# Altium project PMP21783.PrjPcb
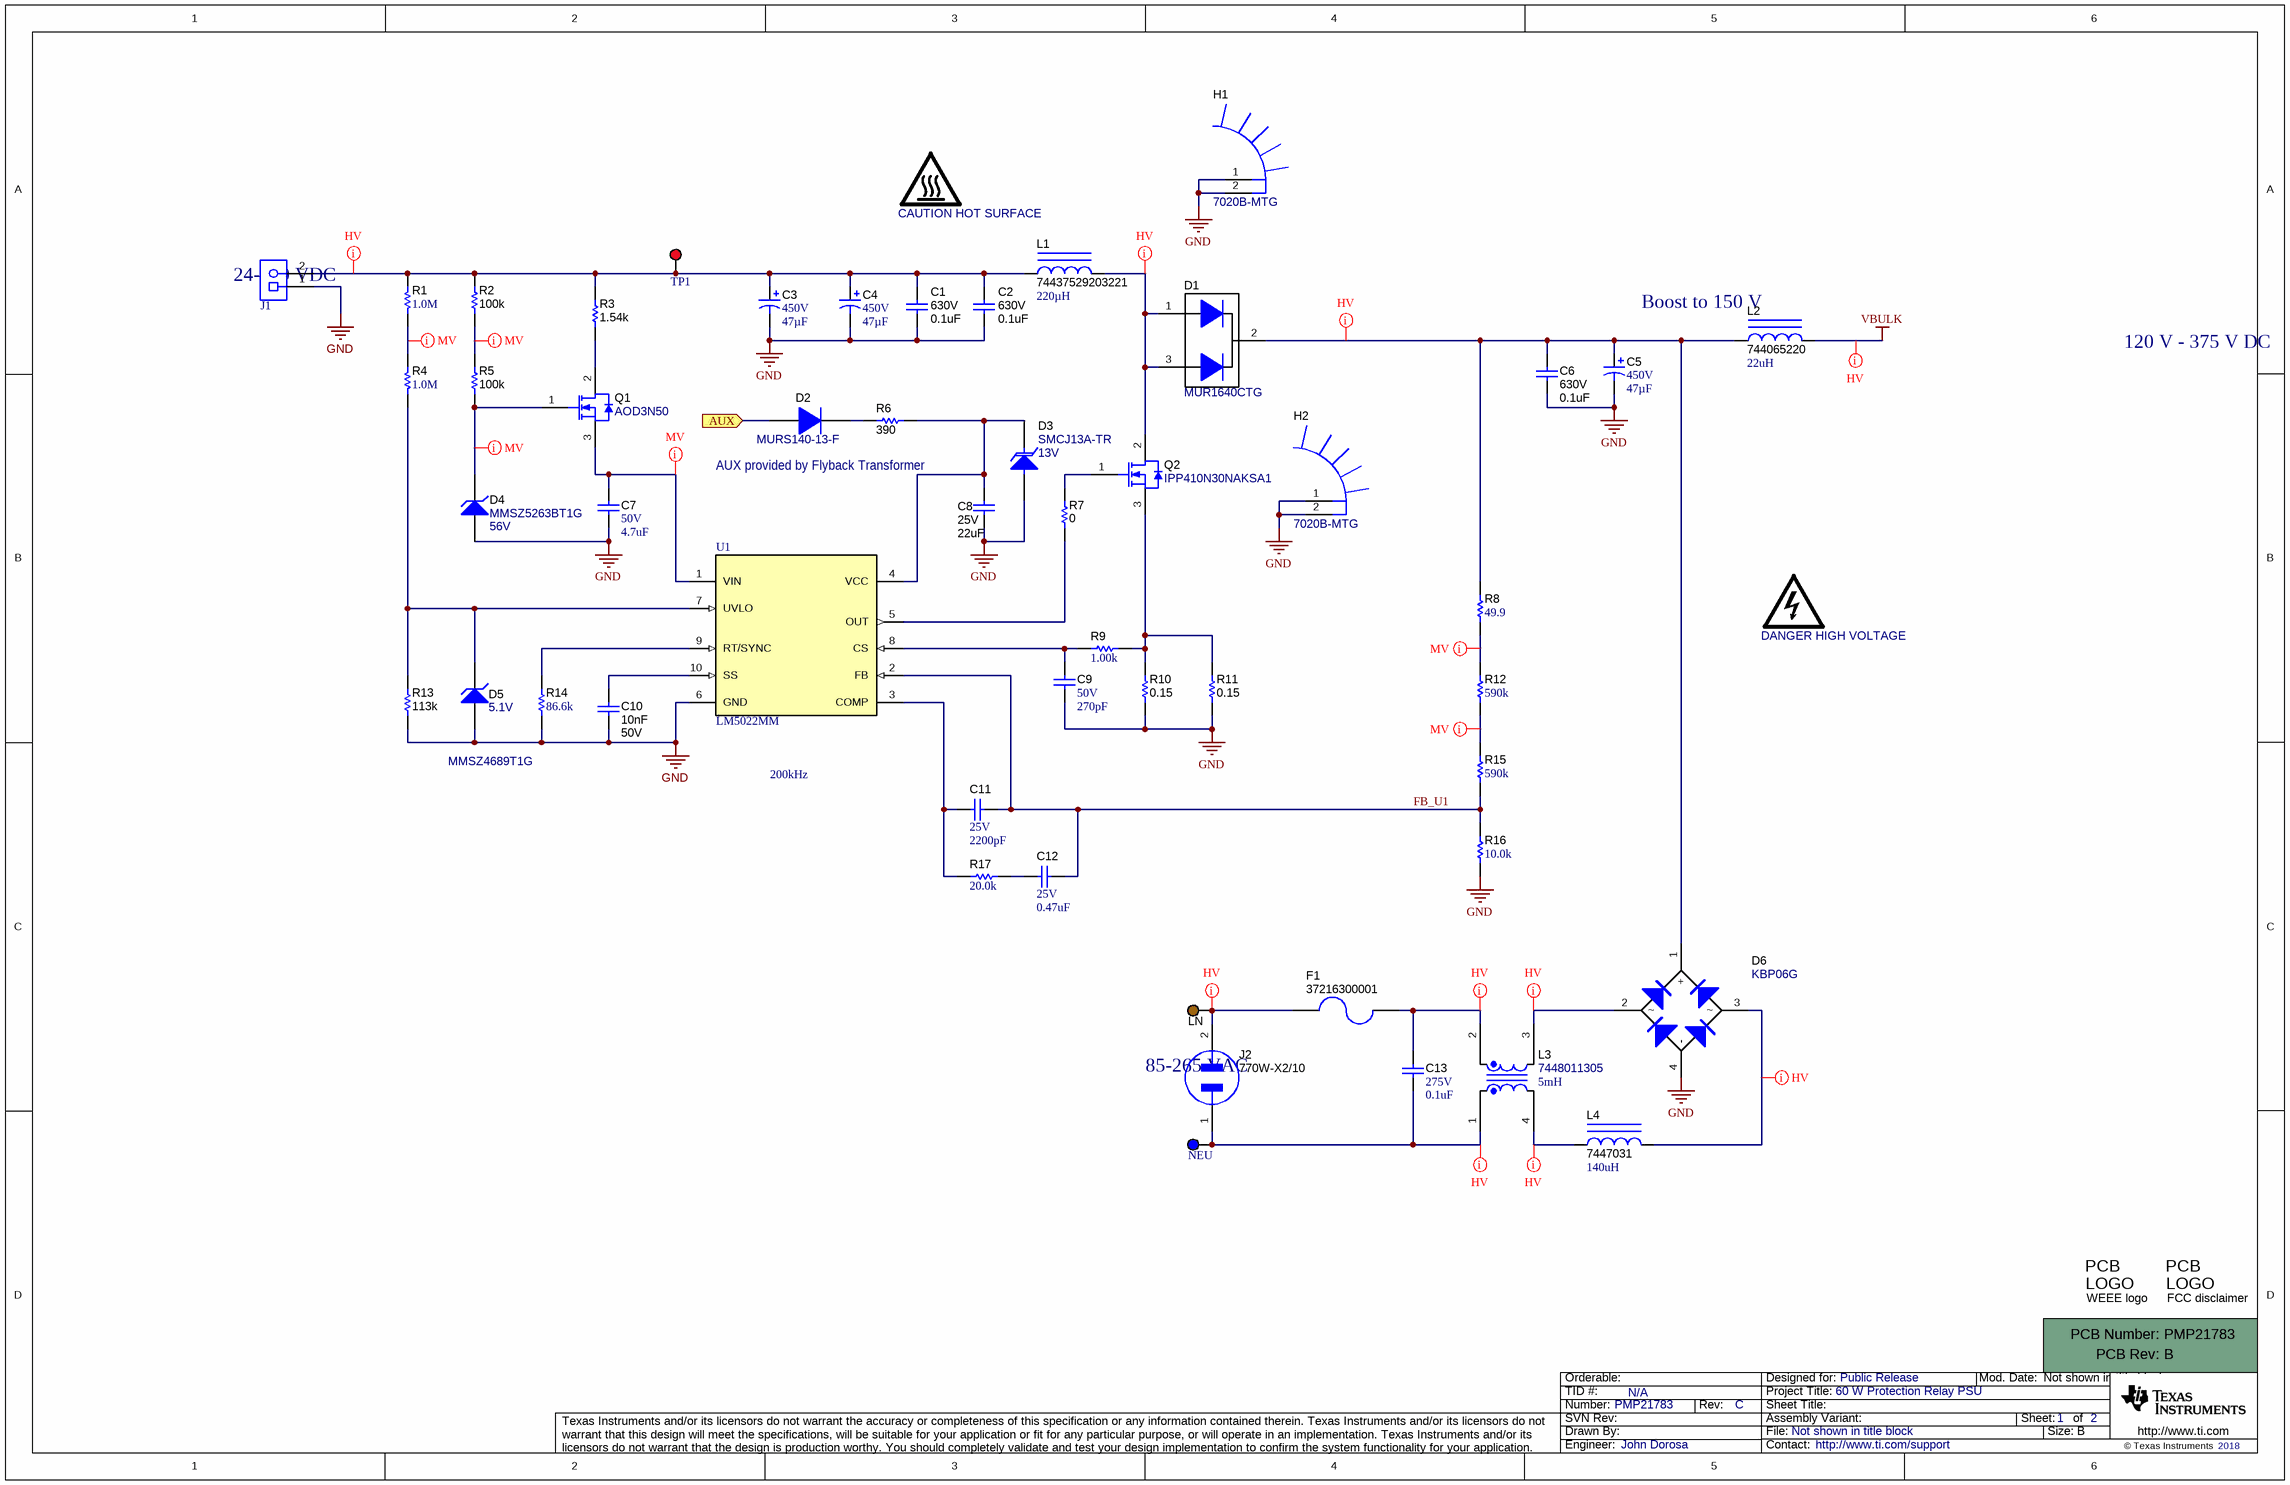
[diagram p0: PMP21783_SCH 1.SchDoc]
TID: N/A; TechSupport: http://www.ti.com/support; SCH_Rev: C; PRJ_Title: 60 W Protection Relay PSU; PRJ_Number: PMP21783; PRJ_Engineer: John Dorosa; PRJ_Customer: Public Release; PCB_Rev: B; PCB_Layout: John Dorosa; CopyrightYear: 2018
2 sheets, 146 parts. Net scope: flat (ports and power ports of the same name join across sheets).
Board file: PMP21783_PCB.PcbDoc
Sheets:
  PMP21783_SCH 1.SchDoc
  PMP21783_SCH 2.SchDoc

## Sheet PMP21783_SCH 1.SchDoc
size 431 x 279 mm; Date: Not shown in title block; ApprovedBy: Not shown in title block; CheckedBy: Not shown in title block; Author: Not shown in title block; CompanyName: Not shown in title block; Engineer: Not shown in title block; Organization: Not shown in title block; Address1: Not shown in title block; Address2: Not shown in title block; Address3: Not shown in title block; Address4: Not shown in title block; DocumentNumber: 1; Revision: Use project parameter SCH_Rev; SheetNumber: 1; SheetTotal: 2; PageSetup: Record=PageOptions¦CenterHorizontal=True¦CenterVertical=True¦PrintScale=1.00¦XCorrection=1.00¦YCorrection=1.00¦PrintKind=0¦BorderSize=5000000¦LeftOffset=0¦BottomOffset=0¦Orientation=2¦PaperLength=1000¦PaperWidth=1000¦Scale=100¦PaperSource=15¦PrintQuality=600¦MediaType=1¦DitherType=10¦PaperKind=Letter¦PrintScaleMode=1

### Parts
!PCB1  Printed Circuit Board  (value not drawn)  (mechanical)
C1  VDC_V: 630V  ValueDisplayed: 0.1uF  [1210_280]  (hidden comment: C1210C104KBRAC7800)
C2  VDC_V: 630V  ValueDisplayed: 0.1uF  [1210_280]  (hidden comment: C1210C104KBRAC7800)
C3  VDC_V: 450V  ValueDisplayed: 47µF  [BXW_1250x3500]  (hidden comment: 450BXW47MEFC12.5X35)
C4  VDC_V: 450V  ValueDisplayed: 47µF  [BXW_1250x3500]  (hidden comment: 450BXW47MEFC12.5X35)
C5  VDC_V: 450V  ValueDisplayed: 47µF  [BXW_1250x3500]  (hidden comment: 450BXW47MEFC12.5X35)
C6  VDC_V: 630V  ValueDisplayed: 0.1uF  [1210_280]  (hidden comment: C1210C104KBRAC7800)
C7  VDC_V: 50V  ValueDisplayed: 4.7uF  [1206_180]  (hidden comment: GRM31CR71H475KA12L)
C8  VDC_V: 25V  ValueDisplayed: 22uF  [1206_190]  (hidden comment: EMK316BB7226ML-T)
C9  VDC_V: 50V  ValueDisplayed: 270pF  [0603]  (hidden comment: GRM188R71H271KA01D)
C10  Cap_F: 10nF  VDC_V: 50V  [0603]  (hidden comment: GRM188R71H103KA01D)
C11  VDC_V: 25V  ValueDisplayed: 2200pF  [0603]  (hidden comment: GRM188R71E222KA01D)
C12  VDC_V: 25V  ValueDisplayed: 0.47uF  [0603]  (hidden comment: GRM188R71E474KA12D)
C13  VDC_V: 275V  ValueDisplayed: 0.1uF  [WCAP-FTX2_1800x600x1200]  (hidden comment: 890324025017)
D1  MUR1640CTG  [TO-220AB]
D2  MURS140-13-F  [SMB]
D3  SMCJ13A-TR  value 13V  [SMC]
D4  MMSZ5263BT1G  value 56V  [SOD-123]
D5  MMSZ4689T1G  value 5.1V  [SOD-123]
D6  KBP06G  [KBP]
F1  37216300001  [FUSE_372]
H1  7020B-MTG  [FP-7020B-MTG_HEAT_SINK_TO220-MFG]
H2  7020B-MTG  [FP-7020B-MTG_HEAT_SINK_TO220-MFG]
J1  ED120/2DS  [On-Shore_ED120_2DS]  (value not drawn)
J2  770W-X2/10  [CONN_AC_770W-SERIES]
L1  74437529203221  ValueDisplayed: 220µH  [WE-HCF Round_2920]
L2  744065220  ValueDisplayed: 22uH  [WE-TPC-XLH2]
L3  7448011305  value 5mH  [WE-CMBNC_XS]
L4  7447031  ValueDisplayed: 140uH  [WE-FI_1350x700]
LN  5125  [Keystone5125]  (value not drawn)
LOGO1  CAUTION HOT SURFACE  [IEC_HotSurface_Medium]  (no BOM)
LOGO2  DANGER HIGH VOLTAGE  [IEC_HighVoltage_Medium]  (no BOM)
Logo3  WEEE logo  [WEEE_Minimum]  (no BOM)
Logo4  FCC disclaimer  [FCC_disclaimer]  (no BOM)
NEU  5127  [Keystone5127]  (value not drawn)
Q1  AOD3N50  [DPAK]
Q2  IPP410N30NAKSA1  [TO-220-3]
R1  ValueDisplayed: 1.0M  [1206]  (hidden comment: CRCW12061M00JNEA)
R2  ValueDisplayed: 100k  [1206]  (hidden comment: CRCW1206100KJNEA)
R3  ValueDisplayed: 1.54k  [1206]  (hidden comment: CRCW12061K54FKEA)
R4  ValueDisplayed: 1.0M  [1206]  (hidden comment: CRCW12061M00JNEA)
R5  ValueDisplayed: 100k  [1206]  (hidden comment: CRCW1206100KJNEA)
R6  ValueDisplayed: 390  [1206]  (hidden comment: RC1206FR-07390RL)
R7  ValueDisplayed: 0  [0805_HV]  (hidden comment: MCR10EZPJ000)
R8  ValueDisplayed: 49.9  [1206]  (hidden comment: RC1206FR-0749R9L)
R9  ValueDisplayed: 1.00k  [0603]  (hidden comment: CRCW06031K00FKEA)
R10  ValueDisplayed: 0.15  [2010]  (hidden comment: CSR2010FTR150)
R11  ValueDisplayed: 0.15  [2010]  (hidden comment: CSR2010FTR150)
R12  ValueDisplayed: 590k  [1206]  (hidden comment: CRCW1206590KFKEA)
R13  ValueDisplayed: 113k  [0603]  (hidden comment: CRCW0603113KFKEA)
R14  ValueDisplayed: 86.6k  [0603]  (hidden comment: CRCW060386K6FKEA)
R15  ValueDisplayed: 590k  [1206]  (hidden comment: CRCW1206590KFKEA)
R16  ValueDisplayed: 10.0k  [0603]  (hidden comment: CRCW060310K0FKEA)
R17  ValueDisplayed: 20.0k  [0603]  (hidden comment: CRCW060320K0FKEA)
TP1  5010  [Keystone5010]  (value not drawn)
U1  LM5022MM  [DGS0010A_N]

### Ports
AUX (in)

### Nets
GND: C1.2 C2.2 C3.2(-) C4.2(-) C5.2(-) C6.2 C7.2 C8.2 C9.2 C10.2 D3.2(A) D4.2(A) D5.2(A) D6.4(-) H1.1 H1.2 H2.1 H2.2 J1.1 R10.1 R11.1 R13.1 R14.1 R16.1 U1.6(GND)
VBULK: L2.2
AUX: D2.2(A) ; port AUX
FB_U1: C11.1 C12.1 R15.1 R16.2 U1.2(FB)
NetC1_1: C1.1 C2.1 C3.1(+) C4.1(+) J1.2 L1.1 R1.1 R2.2 R3.2 TP1.1
NetC5_1: C5.1(+) C6.1 D1.2(K) D6.1(+) L2.1 R8.2
NetC7_1: C7.1 Q1.3(S) U1.1(VIN)
NetC8_1: C8.1 D3.1(K) R6.2 U1.4(VCC)
NetC9_1: C9.1 R9.1 U1.8(CS)
NetC10_1: C10.1 U1.10(SS)
NetC11_2: C11.2 R17.1 U1.3(COMP)
NetC12_2: C12.2 R17.2
NetC13_1: C13.1 F1.1 L3.2
NetC13_2: C13.2 J2.1(Neutral) L3.1 NEU.1
NetD1_1: D1.1(A) D1.3(A) L1.2 Q2.2(D)
NetD2_1: D2.1(K) R6.1
NetD4_1: D4.1(K) Q1.1(G) R5.1
NetD5_1: D5.1(K) R4.2 R13.2 U1.7(UVLO)
NetD6_2: D6.2 L3.3
NetD6_3: D6.3 L4.2
NetF1_2: F1.2 J2.2(Hot) LN.1
NetL3_4: L3.4 L4.1
NetQ1_2: Q1.2(D) R3.1
NetQ2_1: Q2.1(G) R7.2
NetQ2_3: Q2.3(S) R9.2 R10.2 R11.2
NetR1_2: R1.2 R4.1
NetR2_1: R2.1 R5.2
NetR7_1: R7.1 U1.5(OUT)
NetR8_1: R8.1 R12.2
NetR12_1: R12.1 R15.2
NetR14_2: R14.2 U1.9(RT/SYNC)

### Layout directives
mark named HV: NetC1_1, NetC5_1, NetC13_1, NetC13_2, NetD1_1, NetD6_2, NetD6_3, NetF1_2, NetL3_4, VBULK
mark named MV: NetC7_1, NetD4_1, NetR1_2, NetR2_1, NetR8_1, NetR12_1

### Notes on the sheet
- 24-250 VDC
- Boost to 150 V
- 120 V - 375 V DC
- AUX provided by Flyback Transformer
- 200kHz
- 85-265 VAC

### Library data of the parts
!PCB1 = CMP-0003618-2: Manufacturer: Any; PartNumber: PMP21783
C1 C2 C6 = CMP-0009076-1: CAP, CERM, 0.1 uF, 630 V, +/- 10%, X7R, 1210; Manufacturer: Kemet; TaMin_C: -55°C; Polarized: N; SizeAreaWB_mm2: 14.7; Value1: Unknown; U/M: EA; Value: 0.1uF; TaMax_C: 125°C; SizeZ_mm: 2.8; SizeX_mm: 3.2; SizeY_mm: 2.5; Cap_Case: 1210; SizeArea_mm2: 8; Cap_F: 100nF; AEC Category: Q200
C3-C5 = CMP-0078361-1: CAP, AL, 47 µF, 450 V, +/- 20%, TH; Manufacturer: Rubycon; IRMS_A: 1.2A; SizeAreaWB_mm2: 210.25; SizeArea_mm2: 156.25; AEC Qualified: N; AEC Category: Q200; Value: 47uF; TaMax_C: 105°C; SizeZ_mm: 37; Polarized: Y; TaMin_C: -25°C; SizeY_mm: 12.5; U/M: EA; CompType: Capacitor; Cap_Case: 12.5x35mm
C7 = CMP-0008969-2: CAP, CERM, 4.7 uF, 50 V, +/- 10%, X7R, 1206; Manufacturer: MuRata; TaMin_C: -55°C; Polarized: N; SizeAreaWB_mm2: 10.92; Value1: Unknown; U/M: EA; Value: 4.7uF; TaMax_C: 125°C; SizeZ_mm: 1.8; SizeX_mm: 3.2; SizeY_mm: 1.6; Cap_Case: 2220; SizeArea_mm2: 5.12; Cap_F: 4.7µF; AEC Category: Q200
C8 = CMP-0008805-2: CAP, CERM, 22 uF, 25 V, +/- 20%, X7R, 1206_190; Manufacturer: Taiyo Yuden; TaMin_C: -55°C; Polarized: N; SizeAreaWB_mm2: 10.92; Value1: Unknown; U/M: EA; Value: 22uF; TaMax_C: 125°C; SizeZ_mm: 1.9; SizeX_mm: 3.2; SizeY_mm: 1.6; Cap_Case: 1206; Value2: 16V; SizeArea_mm2: 5.12; Cap_F: 22µF; AEC Category: Q200
C9 = CMP-0007446-5: CAP, CERM, 270 pF, 50 V, +/- 10%, X7R, 0603; Manufacturer: MuRata; TaMin_C: -55°C; Polarized: N; SizeAreaWB_mm2: 4.68; Value1: Unknown; U/M: EA; Value: 270pF; TaMax_C: 125°C; SizeZ_mm: 1; SizeX_mm: 1.6; SizeY_mm: 0.8; SizeArea_mm2: 1.28; AEC Category: Q200
C10 = CMP-0007433-4: CAP, CERM, 0.01 uF, 50 V, +/- 10%, X7R, 0603; Manufacturer: MuRata; TaMin_C: -55°C; Polarized: N; SizeAreaWB_mm2: 4.68; Value1: Unknown; U/M: EA; Value: 0.01uF; TaMax_C: 125°C; SizeZ_mm: 1; SizeX_mm: 1.6; SizeY_mm: 0.8; SizeArea_mm2: 1.28; AEC Category: Q200
C11 = CMP-0007414-4: CAP, CERM, 2200 pF, 25 V, +/- 10%, X7R, 0603; Manufacturer: MuRata; TaMin_C: -55°C; Polarized: N; SizeAreaWB_mm2: 4.68; Value1: Unknown; U/M: EA; Value: 2200pF; TaMax_C: 125°C; SizeZ_mm: 1; SizeX_mm: 1.6; SizeY_mm: 0.8; SizeArea_mm2: 1.28; Cap_F: 2.2nF; AEC Category: Q200
C12 = CMP-0007424-4: CAP, CERM, 0.47 uF, 25 V, +/- 10%, X7R, 0603; Manufacturer: MuRata; TaMin_C: -55°C; Polarized: N; SizeAreaWB_mm2: 4.68; Value1: Unknown; U/M: EA; Value: 0.47uF; TaMax_C: 125°C; SizeZ_mm: 1; SizeX_mm: 1.6; SizeY_mm: 0.8; SizeArea_mm2: 1.28; Cap_F: 470nF; AEC Category: Q200
C13 = CMP-0012314-3: CAP, Film, 0.1 uF, 275 V, +/- 10%, TH; Manufacturer: Wurth Elektronik; TaMin_C: -40°C; Polarized: N; Value1: Unknown; Value: 0.1uF; TaMax_C: 105°C; Cap_Case: 18x6x12mm; Cap_F: 100nF; AEC Category: Q200
D1 = CMP-0085336-1: Diode, Ultrafast, 400 V, 8 A, TO-220AB; Manufacturer: ON Semiconductor; Value1: 8A; Value2: 16V; TJmax_C: 175°C; SizeX_mm: 10.2; AEC Qualified: N; SizeY_mm: 4.5; SizeArea_mm2: 45.9; AEC Category: Q101; Value: 400V; RJC_CperW: 2; SizeZ_mm: 19.4; SizeAreaWB_mm2: 79.3
D2 = CMP-0029027-2: Diode, Ultrafast, 400 V, 1 A, SMB; Manufacturer: Diodes Inc.; SizeX_mm: 5.6; SizeZ_mm: 2.6; SizeY_mm: 3.81; Value2: 1.25V; SizeArea_mm2: 21.336; TJmax_C: 150°C; AEC Category: Q101; Green_Lifecycle: Active; Value1: 1A; Green_REACh: Passed; SizeAreaWB_mm2: 44.156; Value: 400V; RJC_CperW: 13
D3 = CMP-0085423-1: Diode, TVS, Uni, 13 V, 21.5 Vc, 1500 W, 73 A, SMC; Manufacturer: STMicroelectronics; SizeAreaWB_mm2: 83.2686; SizeZ_mm: 2.62; SizeY_mm: 6.22; Ipp: 73A; Ppk: 1.5kW; RJA_CperW: 90; SizeArea_mm2: 50.5686; SizeX_mm: 8.13; Value1: 21.5V; Vbr_Min: 14.4V; AEC Qualified: N; AEC Category: Q101
D4 = CMP-0005738-4: Diode, Zener, 56 V, 500 mW, AEC-Q101, SOD-123; Manufacturer: ON Semiconductor; AEC Qualified: Y; Value1: 0.5W; SizeY_mm: 1.7; SizeX_mm: 3.85; SizeArea_mm2: 6.545; AEC Category: Q101; SizeAreaWB_mm2: 13.095; Power_W: 500mW; SizeZ_mm: 1.35; RJA_CperW: 340
D5 = CMP-0005786-3: Diode, Zener, 5.1 V, 500 mW, SOD-123; Manufacturer: ON Semiconductor; RJA_CperW: 340; AEC Category: Q101; Power_W: 500mW; Value1: 0.5W; SizeX_mm: 3.85; SizeY_mm: 1.7; SizeZ_mm: 1.35; SizeAreaWB_mm2: 13.095; SizeArea_mm2: 6.545
D6 = CMP-0029224-3: Diode, Switching-Bridge, 600 V, 1.5 A, TH; Manufacturer: Diodes Inc.; Value2: 1.1V; AEC Category: Q101; SizeAreaWB_mm2: 79.75; Value: 600V; Io_A: 1.5A; RJC_CperW: 18; SizeY_mm: 3.5; Green_Lifecycle: Not Set; SizeX_mm: 12.5; SizeZ_mm: 12.69; TJmax_C: 150°C; SizeArea_mm2: 43.75; Green_REACh: Incomplete
F1 = CMP-0003560-2: Fuse, 6.3 A, 250VAC/VDC, TH; Manufacturer: Littelfuse; Irating_A: 6.3A; VAC_V: 250V
H1 H2 = CMP-0086466-3: Heat Sink TO-220 Aluminum 8.0W @ 70°C Board Level, Vertical; Manufacturer: Aavid Thermalloy
J1 = CMP-0074910-1: Terminal Block, 5.08 mm, 2x1, Brass, TH; Manufacturer: On-Shore Technology; Cert_VDE: Y; CNHeader: False; Current_A: 15A; Green_Lifecycle: Not Set; Shrouded: N; Gender: Female; Green_REACh: Incomplete; Voltage_V: 300V; Row_Count: 1; Pitch_mm: 5.08; CT: True
J2 = CMP-0074930-1: AC Receptacle, 2.5A, R/A, TH; Manufacturer: Qualtek Electronics Corporation; CNHeader: False; Green_Lifecycle: Not Set; Green_REACh: Incomplete
L1 = CMP-0085391-1: Inductor, Shielded, Mn-Zn, 220 µH, 5.3 A, 0.040095 ohm, SMD; Manufacturer: Wurth Elektronik; AEC Qualified: N; Value: 220uH; Imax_A: 5.3A; SizeZ_mm: 20.5; Irms: 8.8A @ 50C rise; SizeAreaWB_mm2: 810; AEC Category: Q200; SizeX_mm: 25; Isat: 5.3A @ 30% inductance drop; SizeY_mm: 28; SizeArea_mm2: 700
L2 = CMP-0064437-2: Inductor, Shielded Drum Core, Ferrite, 22 uH, 1.8 A, 0.11 ohm, SMD; Manufacturer: Wurth Elektronik; Isat: 1.9A @ 35% inductance drop; Irms: 1.8A @ 30C rise; Green_Lifecycle: Active; SizeAreaWB_mm2: 144; DCR_ohm: 0.11; Green_REACh: Passed; Value: 22uH; Imax_A: 1.8A; SizeZ_mm: 2.8; SizeX_mm: 10; SizeArea_mm2: 100; Ind_H: 22µH; AEC Category: Q200
L3 = CMP-0076875-1: Coupled inductor, 5 mH, 1.3 A, 0.2 ohm, TH; Manufacturer: Wurth Elektronik; AEC Category: Q200; DCR_ohm: 0.2
L4 = CMP-0064732-2: Inductor, Toroid, Powdered Iron, 140 uH, 1 A, 0.11 ohm, TH; Manufacturer: Wurth Elektronik; Irms: 1A @ 40C rise; Green_Lifecycle: Active; SizeAreaWB_mm2: 139.5; DCR_ohm: 0.11; Green_REACh: Passed; Value: 140uH; Imax_A: 1A; SizeZ_mm: 13.5; SizeX_mm: 7; SizeArea_mm2: 94.5; Ind_H: 140µH; AEC Qualified: N; AEC Category: Q200
LN = CMP-0055157-1: Test Point, Multipurpose, Brown, TH; Manufacturer: Keystone; CNHeader: FALSE; Green_Lifecycle: Active; Green_REACh: Passed; ContactFinish: Silver; CT: TRUE
LOGO1 = CMP-0074837-1: IEC 61010-1 Hot Surface Warning; SymbolCreator: a0412235
LOGO2 = CMP-0074835-1: IEC 61010-1 High Voltage Warning; SymbolCreator: a0412235
Logo3 = CMP-0074769-1
Logo4 = CMP-0074847-1: FCC_disclaimer; Library Reference: Logo
NEU = CMP-0055156-1: Test Point, Multipurpose, Blue, TH; Manufacturer: Keystone; CNHeader: FALSE; Green_Lifecycle: Active; Green_REACh: Passed; ContactFinish: Silver; CT: TRUE
Q1 = CMP-0001119-4: MOSFET, N-CH, 500 V, 2.8 A, DPAK; Alternate Manufacturer: None; Manufacturer: AOS; ChType: N; SizeY_mm: 6.54; SizeAreaWB_mm2: 101.7114; SizeX_mm: 9.91; SizeArea_mm2: 64.8114; QgTyp_nC: 6.7; ChMode: Enhancement; SizeZ_mm: 2.29; AEC Category: Q101; Vgs_V: 30V; Value: 500V; Value2: 6.7 nC; IdsMax_A: 2.8A
Q2 = CMP-0085354-1: MOSFET, N-CH, 300 V, 44 A, TO-220-3; Alternate Manufacturer: None; Manufacturer: Infineon Technologies; SizeAreaWB_mm2: 127.3152; IdsMax_A: 44A; VdsMax_V: 300V; Vgs_V: 20V; Value2: 65 nC; SizeZ_mm: 20.68; AEC Category: Q101; Value: 300V; ChType: N; Value1: ? ohm; SizeY_mm: 10.16; QgTyp_nC: 65; SizeArea_mm2: 86.0552; ChMode: Enhancement; SizeX_mm: 8.47
R1 R4 = CMP-0018610-3: RES, 1.0 M, 5%, 0.25 W, AEC-Q200 Grade 0, 1206; Manufacturer: Vishay-Dale; Power_W: 250mW; TempCo: 200 ppm/C; Value_Code: 1M00; Value: 1.0Meg; EIA_Code: E24; Res_ohm: 1M; SizeX_mm: 3.2; SizeY_mm: 1.6; SizeZ_mm: 1.35; Value2: 0.25W; SizeArea_mm2: 5.12; AEC Qualified: Y; VDC_V: 200V; AEC Category: Q200; AEC Grade: 0
R2 R5 = CMP-0018574-3: RES, 100 k, 5%, 0.25 W, AEC-Q200 Grade 0, 1206; Manufacturer: Vishay-Dale; Power_W: 250mW; TempCo: 200 ppm/C; Value: 100k; EIA_Code: E24; SizeX_mm: 3.2; SizeY_mm: 1.6; SizeZ_mm: 1.35; Value2: 0.25W; SizeArea_mm2: 5.12; AEC Qualified: Y; VDC_V: 200V; AEC Category: Q200; AEC Grade: 0
R3 = CMP-0016705-3: RES, 1.54 k, 1%, 0.25 W, AEC-Q200 Grade 0, 1206; Manufacturer: Vishay-Dale; Power_W: 250mW; TempCo: 100 ppm/C; Value_Code: 1k54; Value: 1.54k; EIA_Code: E96; SizeX_mm: 3.2; SizeY_mm: 1.6; SizeZ_mm: 1.35; Value2: 0.25W; SizeArea_mm2: 5.12; AEC Qualified: Y; VDC_V: 200V; AEC Category: Q200; AEC Grade: 0
R6 = CMP-0018242-2: RES, 390, 1%, 0.25 W, 1206; Manufacturer: Yageo America; Power_W: 250mW; TempCo: 100 ppm/C; Value_Code: 390R; U/M: EA; Value: 390; SizeX_mm: 3.2; SizeY_mm: 1.6; SizeZ_mm: 1.35; Value2: 0.25W; SizeArea_mm2: 5.12; VDC_V: 200V; AEC Category: Q200
R7 = CMP-0020802-2: RES, 0, 5%, 0.125 W, 0805; Manufacturer: Rohm; Power_W: 125mW; TempCo: 400 ppm/C; Value_Code: 0000; U/M: EA; Value: 0; EIA_Code: E24; SizeX_mm: 2; SizeY_mm: 1.25; SizeZ_mm: 1.45; Value2: 0.125W; SizeArea_mm2: 2.5; VDC_V: 150V; AEC Category: Q200
R8 = CMP-0018328-2: RES, 49.9, 1%, 0.25 W, 1206; Manufacturer: Yageo America; Power_W: 250mW; TempCo: 100 ppm/C; Value_Code: 49R9; U/M: EA; Value: 49.9; EIA_Code: E96; SizeX_mm: 3.2; SizeY_mm: 1.6; SizeZ_mm: 1.35; Value2: 0.25W; SizeArea_mm2: 5.12; VDC_V: 200V; AEC Category: Q200
R9 = CMP-0022109-5: RES, 1.00 k, 1%, 0.1 W, AEC-Q200 Grade 0, 0603; Manufacturer: Vishay-Dale; Power_W: 100mW; TempCo: 100 ppm/C; Value_Code: 1k00; Value: 1.00k; EIA_Code: E96; Res_ohm: 1k; SizeX_mm: 1.6; SizeY_mm: 0.8; SizeZ_mm: 1; Value2: 0.1W; SizeArea_mm2: 1.28; AEC Qualified: Y; VDC_V: 75V; AEC Category: Q200; AEC Grade: 0
R10 R11 = CMP-0016513-2: RES, 0.15, 1%, 1 W, 2010; Manufacturer: Stackpole Electronics Inc; Power_W: 1W; TempCo: 100 ppm/C; Value_Code: R150; U/M: EA; Value: 0.15; EIA_Code: E96; SizeX_mm: 5; SizeY_mm: 2.5; SizeZ_mm: 1.66; SizeArea_mm2: 12.5; AEC Category: Q200
R12 R15 = CMP-0017074-3: RES, 590 k, 1%, 0.25 W, AEC-Q200 Grade 0, 1206; Manufacturer: Vishay-Dale; Power_W: 250mW; TempCo: 100 ppm/C; Value: 590k; EIA_Code: E96; SizeX_mm: 3.2; SizeY_mm: 1.6; SizeZ_mm: 1.35; Value2: 0.25W; SizeArea_mm2: 5.12; AEC Qualified: Y; VDC_V: 200V; AEC Category: Q200; AEC Grade: 0
R13 = CMP-0022010-4: RES, 113 k, 1%, 0.1 W, AEC-Q200 Grade 0, 0603; Manufacturer: Vishay-Dale; Power_W: 100mW; TempCo: 100 ppm/C; Value: 113k; EIA_Code: E96; SizeX_mm: 1.6; SizeY_mm: 0.8; SizeZ_mm: 1; Value2: 0.1W; SizeArea_mm2: 1.28; AEC Qualified: Y; VDC_V: 75V; AEC Category: Q200; AEC Grade: 0
R14 = CMP-0022628-4: RES, 86.6 k, 1%, 0.1 W, AEC-Q200 Grade 0, 0603; Manufacturer: Vishay-Dale; Power_W: 100mW; TempCo: 100 ppm/C; Value_Code: 86k6; Value: 86.6k; EIA_Code: E96; SizeY_mm: 0.8; SizeZ_mm: 1; Value2: 0.1W; SizeArea_mm2: 1.28; AEC Qualified: Y; VDC_V: 75V; AEC Category: Q200; SizeX_mm: 1.6; AEC Grade: 0
R16 = CMP-0021998-4: RES, 10.0 k, 1%, 0.1 W, AEC-Q200 Grade 0, 0603; Manufacturer: Vishay-Dale; Power_W: 100mW; TempCo: 100 ppm/C; Value_Code: 10k0; Value: 10.0k; EIA_Code: E96; Res_ohm: 10k; SizeX_mm: 1.6; SizeY_mm: 0.8; SizeZ_mm: 1; Value2: 0.1W; SizeArea_mm2: 1.28; AEC Qualified: Y; VDC_V: 75V; AEC Category: Q200; AEC Grade: 0
R17 = CMP-0022204-4: RES, 20.0 k, 1%, 0.1 W, AEC-Q200 Grade 0, 0603; Manufacturer: Vishay-Dale; Power_W: 100mW; TempCo: 100 ppm/C; Value_Code: 20k0; Value: 20.0k; EIA_Code: E96; Res_ohm: 20k; SizeX_mm: 1.6; SizeY_mm: 0.8; SizeZ_mm: 1; Value2: 0.1W; SizeArea_mm2: 1.28; AEC Qualified: Y; VDC_V: 75V; AEC Category: Q200; AEC Grade: 0
TP1 = CMP-0055147-1: Test Point, Multipurpose, Red, TH; Manufacturer: Keystone; CNHeader: FALSE; Green_Lifecycle: Active; Green_REACh: Passed; ContactFinish: Silver; CT: TRUE
U1 = CMP-0073090-1: 60V Low Side Controller for Boost and SEPIC, 10-pin MSOP; Manufacturer: Texas Instruments; PowerWise: Y; PackageTopMarking: ZXTT*5022; CompType: Switcher

## Sheet PMP21783_SCH 2.SchDoc
size 431 x 279 mm; Date: Not shown in title block; ApprovedBy: Not shown in title block; CheckedBy: Not shown in title block; Author: Not shown in title block; CompanyName: Not shown in title block; Engineer: Not shown in title block; Organization: Not shown in title block; Address1: Not shown in title block; Address2: Not shown in title block; Address3: Not shown in title block; Address4: Not shown in title block; DocumentNumber: 2; Revision: Use project parameter SCH_Rev; SheetNumber: 2; SheetTotal: 2; PageSetup: Record=PageOptions¦CenterHorizontal=True¦CenterVertical=True¦PrintScale=1.00¦XCorrection=1.00¦YCorrection=1.00¦PrintKind=0¦BorderSize=5000000¦LeftOffset=0¦BottomOffset=0¦Orientation=2¦PaperLength=1000¦PaperWidth=1000¦Scale=100¦PaperSource=15¦PrintQuality=600¦MediaType=1¦DitherType=10¦PaperKind=Letter¦PrintScaleMode=1
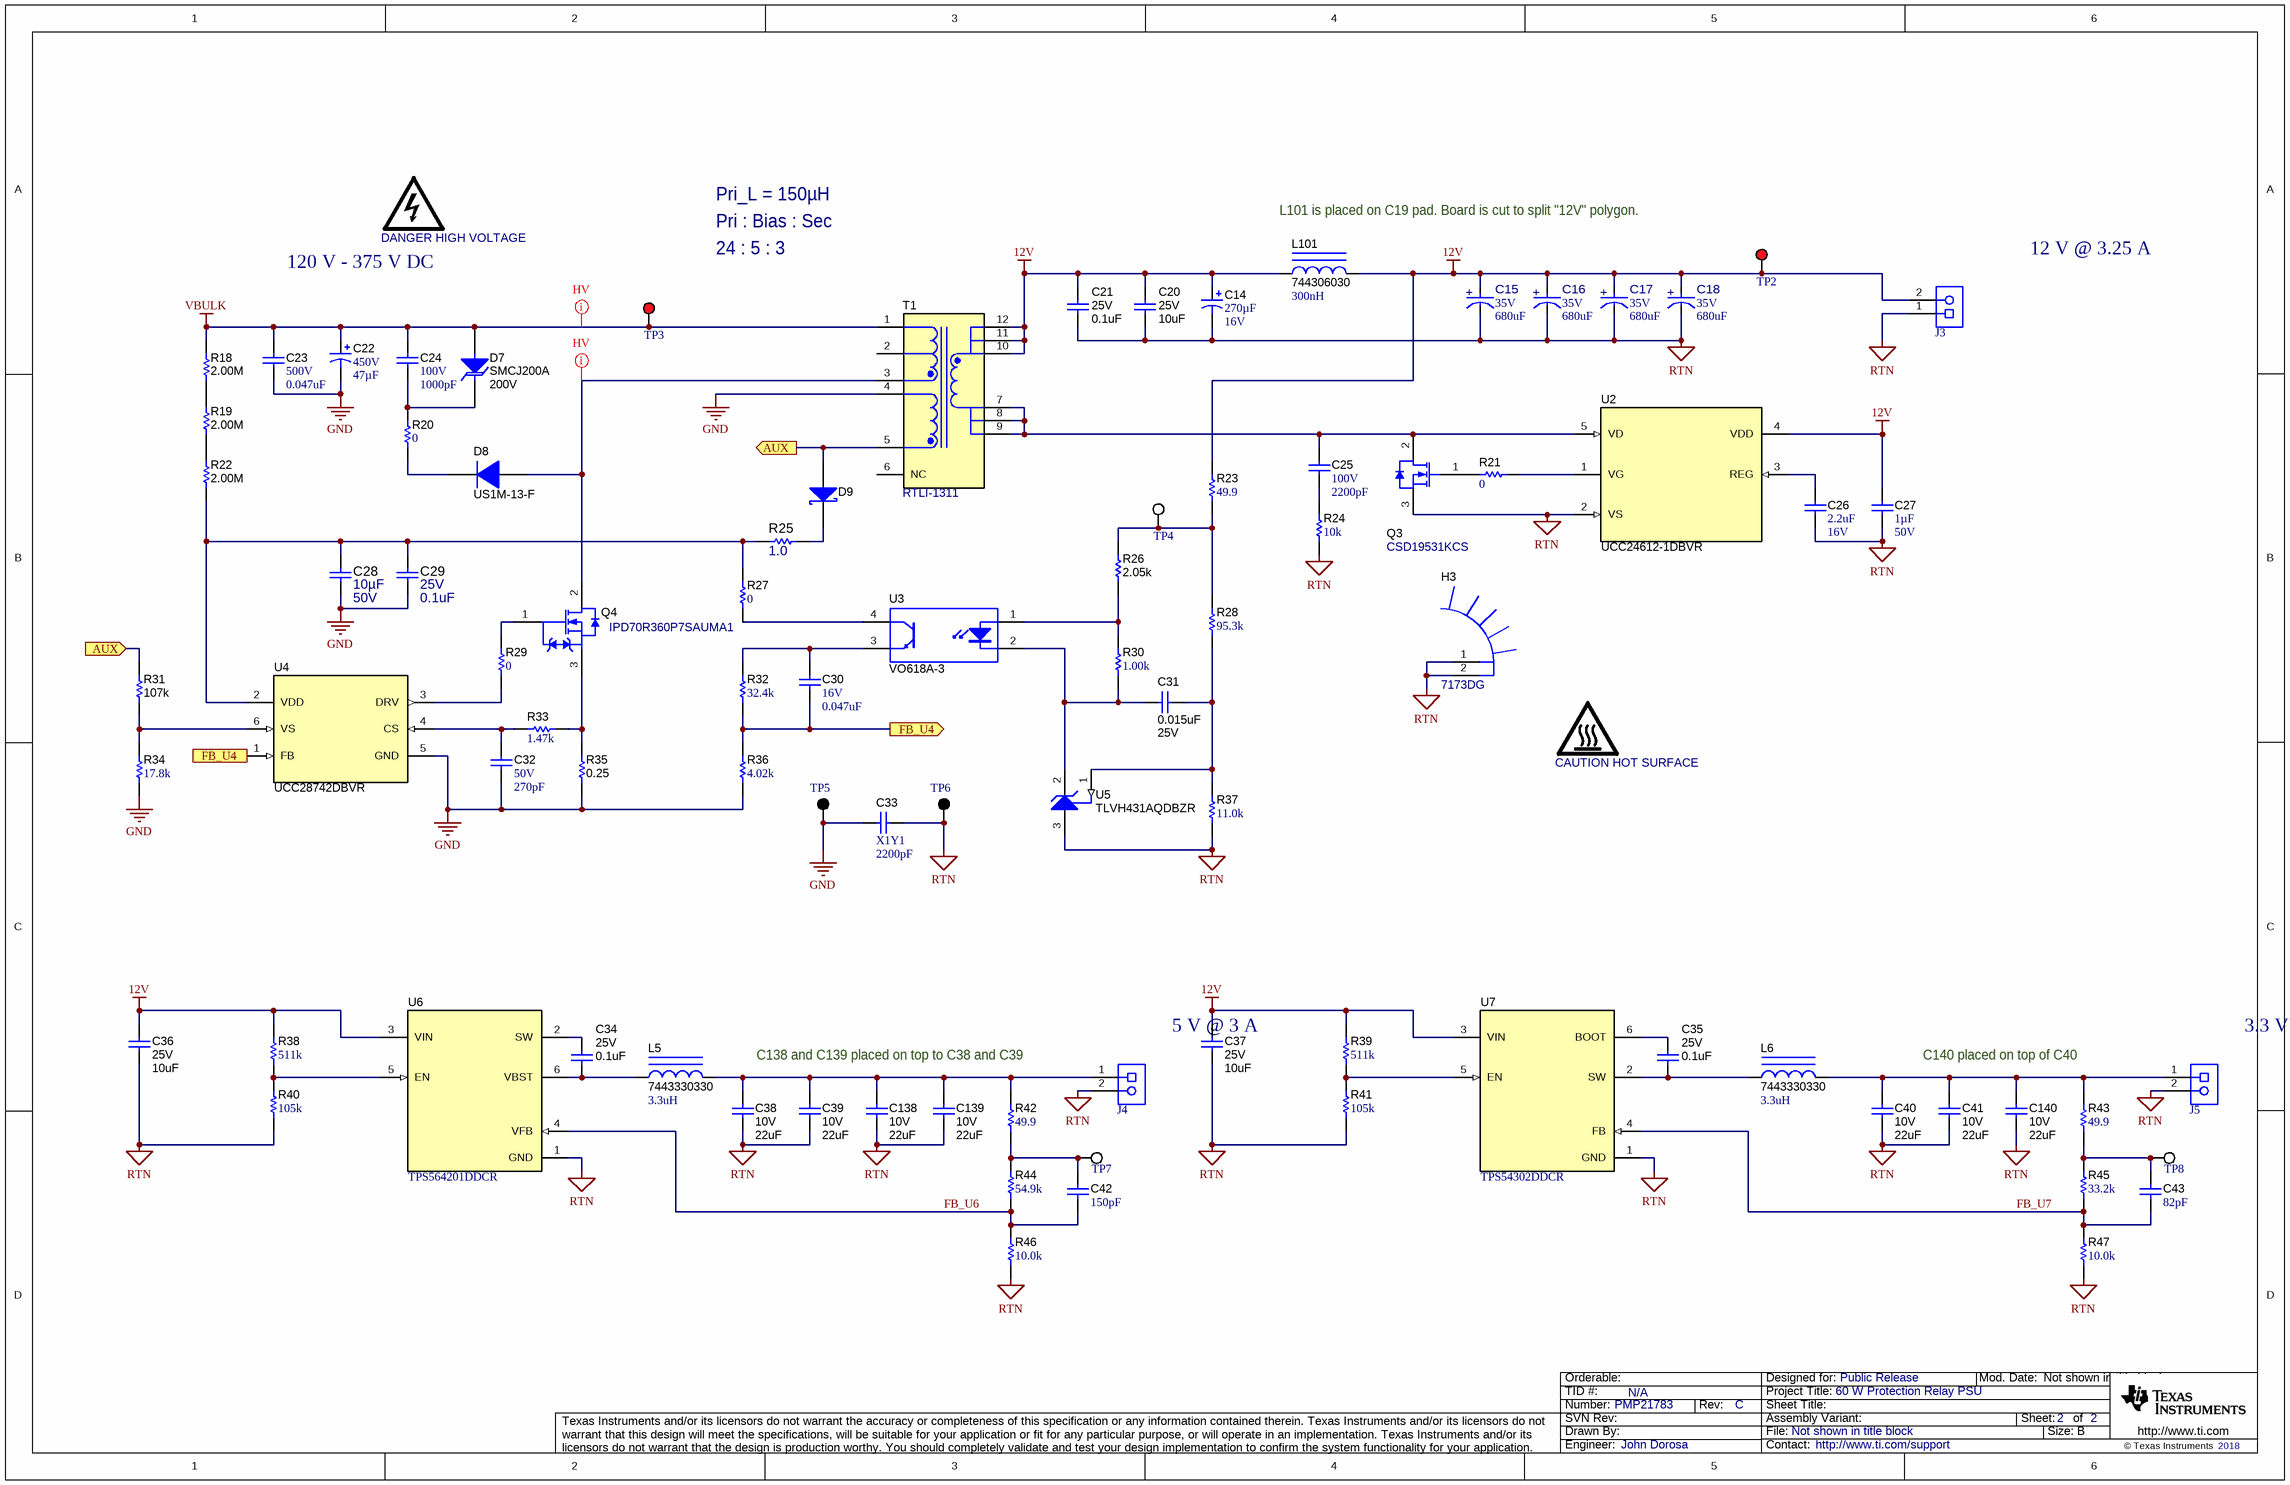
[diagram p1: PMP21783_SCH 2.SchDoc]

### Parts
C14  ValueDisplayed: 270µF  VDC_V: 16V  [R7_1000x1250]  (hidden comment: RR71C271MDN1PH)
C15  VDC_V: 35V  ValueDisplayed: 680uF  [FP-860080578019_RADIAL-MFG]  (hidden comment: 860080578019)
C16  VDC_V: 35V  ValueDisplayed: 680uF  [FP-860080578019_RADIAL-MFG]  (hidden comment: 860080578019)
C17  VDC_V: 35V  ValueDisplayed: 680uF  [FP-860080578019_RADIAL-MFG]  (hidden comment: 860080578019)
C18  VDC_V: 35V  ValueDisplayed: 680uF  [FP-860080578019_RADIAL-MFG]  (hidden comment: 860080578019)
C20  VDC_V: 25V  ValueDisplayed: 10uF  [1210_220]  (hidden comment: GRM32DR71E106KA12L)
C21  VDC_V: 25V  ValueDisplayed: 0.1uF  [0402]  (hidden comment: GRM155R71E104KE14D)
C22  VDC_V: 450V  ValueDisplayed: 47µF  [BXW_1250x3500]  (hidden comment: 450BXW47MEFC12.5X35)
C23  VDC_V: 500V  ValueDisplayed: 0.047uF  [1206]  (hidden comment: VJ1206Y473KXEAT5Z)
C24  VDC_V: 100V  ValueDisplayed: 1000pF  [1206]  (hidden comment: 12061C102JAT2A)
C25  VDC_V: 100V  ValueDisplayed: 2200pF  [0603]  (hidden comment: GRM188R72A222KA01D)
C26  value 2.2uF  VDC_V: 16V  [0805_HV]  (hidden comment: C0805C225K4RACTU)
C27  ValueDisplayed: 1µF  VDC_V: 50V  [0805_HV]  (hidden comment: GCM21BR71H105KA03K)
C28  ValueDisplayed: 10µF  VDC_V: 50V  [1206_190]  (hidden comment: CGA5L1X7R1H106K160AC)
C29  VDC_V: 25V  ValueDisplayed: 0.1uF  [0603]  (hidden comment: C1608X7R1E104K080AA)
C30  VDC_V: 16V  ValueDisplayed: 0.047uF  [0603]  (hidden comment: GRM188R71C473KA01D)
C31  Cap_F: 0.015uF  VDC_V: 25V  [0603]  (hidden comment: GRM188R71E153KA01D)
C32  VDC_V: 50V  ValueDisplayed: 270pF  [0603]  (hidden comment: GRM188R71H271KA01D)
C33  AC_Safety: X1Y1  ValueDisplayed: 2200pF  [C900_9x13]  (hidden comment: C921U222MVVDBA7317)
C34  VDC_V: 25V  ValueDisplayed: 0.1uF  [0402]  (hidden comment: GRM155R71E104KE14D)
C35  VDC_V: 25V  ValueDisplayed: 0.1uF  [0402]  (hidden comment: GRM155R71E104KE14D)
C36  VDC_V: 25V  ValueDisplayed: 10uF  [1210_220]  (hidden comment: GRM32DR71E106KA12L)
C37  VDC_V: 25V  ValueDisplayed: 10uF  [1210_220]  (hidden comment: GRM32DR71E106KA12L)
C38  VDC_V: 10V  ValueDisplayed: 22uF  [0805_HV]  (hidden comment: GRM21BR61A226ME44L)
C39  VDC_V: 10V  ValueDisplayed: 22uF  [0805_HV]  (hidden comment: GRM21BR61A226ME44L)
C40  VDC_V: 10V  ValueDisplayed: 22uF  [0805_HV]  (hidden comment: GRM21BR61A226ME44L)
C41  VDC_V: 10V  ValueDisplayed: 22uF  [0805_HV]  (hidden comment: GRM21BR61A226ME44L)
C42  ValueDisplayed: 150pF  [0603]  (hidden comment: GRM1885C2A151JA01D)
C43  ValueDisplayed: 82pF  [0603]  (hidden comment: GRM1885C2A820JA01D)
C138  VDC_V: 10V  ValueDisplayed: 22uF  [0805_HV]  (hidden comment: GRM21BR61A226ME44L)
C139  VDC_V: 10V  ValueDisplayed: 22uF  [0805_HV]  (hidden comment: GRM21BR61A226ME44L)
C140  VDC_V: 10V  ValueDisplayed: 22uF  [0805_HV]  (hidden comment: GRM21BR61A226ME44L)
D7  SMCJ200A  value 200V  [SMC]
D8  US1M-13-F  [SMA]
D9  PMEG10010ELRX  [SOD-123W]  (value not drawn)
H3  7173DG  [HSINK_7173DG]
J3  691214310002  [Wurth_691214310002]  (value not drawn)
J4  691214310002  [Wurth_691214310002]  (value not drawn)
J5  691214310002  [Wurth_691214310002]  (value not drawn)
L5  7443330330  ValueDisplayed: 3.3uH  [WE-HCC_1090]
L6  7443330330  ValueDisplayed: 3.3uH  [WE-HCC_1090]
L101  744306030  ValueDisplayed: 300nH  [WE-HCM_1052]
LOGO5  DANGER HIGH VOLTAGE  [IEC_HighVoltage_Medium]  (no BOM)
LOGO6  CAUTION HOT SURFACE  [IEC_HotSurface_Medium]  (no BOM)
Q3  CSD19531KCS  [KCS0003B]
Q4  IPD70R360P7SAUMA1  [DPAK]
R18  ValueDisplayed: 2.00M  [0805_HV]  (hidden comment: ERJ-6ENF2004V)
R19  ValueDisplayed: 2.00M  [0805_HV]  (hidden comment: ERJ-6ENF2004V)
R20  ValueDisplayed: 0  [1206]  (hidden comment: CRCW12060000Z0EA)
R21  ValueDisplayed: 0  [0603]  (hidden comment: CRCW06030000Z0EA)
R22  ValueDisplayed: 2.00M  [0805_HV]  (hidden comment: ERJ-6ENF2004V)
R23  ValueDisplayed: 49.9  [0603]  (hidden comment: CRCW060349R9FKEA)
R24  ValueDisplayed: 10k  [1206]  (hidden comment: CRCW120610K0JNEA)
R25  ValueDisplayed: 1.0  [0603]  (hidden comment: CRCW06031R00JNEA)
R26  ValueDisplayed: 2.05k  [0603]  (hidden comment: CRCW06032K05FKEA)
R27  ValueDisplayed: 0  [0603]  (hidden comment: CRCW06030000Z0EA)
R28  ValueDisplayed: 95.3k  [0603]  (hidden comment: CRCW060395K3FKEA)
R29  ValueDisplayed: 0  [0603]  (hidden comment: CRCW06030000Z0EA)
R30  ValueDisplayed: 1.00k  [0603]  (hidden comment: CRCW06031K00FKEA)
R31  ValueDisplayed: 107k  [0603]  (hidden comment: CRCW0603107KFKEA)
R32  ValueDisplayed: 32.4k  [0603]  (hidden comment: CRCW060332K4FKEA)
R33  ValueDisplayed: 1.47k  [0603]  (hidden comment: CRCW06031K47FKEA)
R34  ValueDisplayed: 17.8k  [0603]  (hidden comment: CRCW060317K8FKEA)
R35  ValueDisplayed: 0.25  [2512]  (hidden comment: CSRN2512FKR250)
R36  ValueDisplayed: 4.02k  [0603]  (hidden comment: CRCW06034K02FKEA)
R37  ValueDisplayed: 11.0k  [0603]  (hidden comment: CRCW060311K0FKEA)
R38  ValueDisplayed: 511k  [0603]  (hidden comment: CRCW0603511KFKEA)
R39  ValueDisplayed: 511k  [0603]  (hidden comment: CRCW0603511KFKEA)
R40  ValueDisplayed: 105k  [0603]  (hidden comment: CRCW0603105KFKEA)
R41  ValueDisplayed: 105k  [0603]  (hidden comment: CRCW0603105KFKEA)
R42  ValueDisplayed: 49.9  [0603]  (hidden comment: CRCW060349R9FKEA)
R43  ValueDisplayed: 49.9  [0603]  (hidden comment: CRCW060349R9FKEA)
R44  ValueDisplayed: 54.9k  [0603]  (hidden comment: CRCW060354K9FKEA)
R45  ValueDisplayed: 33.2k  [0603]  (hidden comment: CRCW060333K2FKEA)
R46  ValueDisplayed: 10.0k  [0603]  (hidden comment: CRCW060310K0FKEA)
R47  ValueDisplayed: 10.0k  [0603]  (hidden comment: CRCW060310K0FKEA)
T1  RTLI-1311  [Renco_RTLI-1311]
TP2  5010  [Keystone5010]  (value not drawn)
TP3  5010  [Keystone5010]  (value not drawn)
TP4  5002  [Keystone5002]  (value not drawn)
TP5  5011  [Keystone5011]  (value not drawn)
TP6  5011  [Keystone5011]  (value not drawn)
TP7  5002  [Keystone5002]  (value not drawn)
TP8  5002  [Keystone5002]  (value not drawn)
U2  UCC24612-1DBVR  [DBV0005A_N]
U3  VO618A-3  [DIP-4]
U4  UCC28742DBVR  [DBV0006A_N]
U5  TLVH431AQDBZR  [DBZ0003A_N]
U6  TPS564201DDCR  [DDC0006A_N]
U7  TPS54302DDCR  [DDC0006A_N]

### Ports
AUX (in), AUX (out), FB_U4 (in), FB_U4 (out)

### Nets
12V: C14.1(+) C15.2(ANODE) C16.2(ANODE) C17.2(ANODE) C18.2(ANODE) C20.1 C21.1 C27.1 C36.1 C37.1 J3.2 L101.1 L101.2 R23.2 R38.2 R39.2 T1.10 T1.11 T1.12 TP2.1 U2.4(VDD) U6.3(VIN) U7.3(VIN)
GND: C22.2(-) C23.2 C28.2 C29.1 C32.2 C33.2 R34.1 R35.1 R36.1 T1.4 TP5.1 U4.5(GND)
RTN: C14.2(-) C15.1(CATHODE) C16.1(CATHODE) C17.1(CATHODE) C18.1(CATHODE) C20.2 C21.2 C26.2 C27.2 C33.1 C36.2 C37.2 C38.2 C39.2 C40.2 C41.2 C138.2 C139.2 C140.2 H3.1 H3.2 J3.1 J4.2 J5.2 Q3.3(S) R24.1 R37.1 R40.1 R41.1 R46.1 R47.1 TP6.1 U2.2(VS) U5.3(ANODE) U6.1(GND) U7.1(GND)
VBULK: C22.1(+) C23.1 C24.1 D7.2(A) R18.2 T1.1 TP3.1
AUX: D9.2(A) R31.2 T1.5 ; port AUX
FB_U4: C30.2 R32.1 R36.2 U4.1(FB) ; port FB_U4
FB_U6: C42.1 R44.1 R46.2 U6.4(VFB)
FB_U7: C43.2 R45.1 R47.2 U7.4(FB)
NetC24_2: C24.2 D7.1(K) R20.2
NetC25_1: C25.1 R24.2
NetC25_2: C25.2 Q3.2(D) T1.7 T1.8 T1.9 U2.5(VD)
NetC26_1: C26.1 U2.3(REG)
NetC28_1: C28.1 C29.2 R22.1 R25.2 R27.2 U4.2(VDD)
NetC30_1: C30.1 R32.2 U3.3(E)
NetC31_1: C31.1 R28.1 R37.2 U5.1(REF)
NetC31_2: C31.2 R30.1 U3.2(K) U5.2(CATHODE)
NetC32_1: C32.1 R33.1 U4.4(CS)
NetC34_1: C34.1 U6.2(SW)
NetC34_2: C34.2 L5.1 U6.6(VBST)
NetC35_1: C35.1 U7.6(BOOT)
NetC35_2: C35.2 L6.1 U7.2(SW)
NetC38_1: C38.1 C39.1 C138.1 C139.1 J4.1 L5.2 R42.2
NetC40_1: C40.1 C41.1 C140.1 J5.1 L6.2 R43.2
NetC42_2: C42.2 R42.1 R44.2 TP7.1
NetC43_1: C43.1 R43.1 R45.2 TP8.1
NetD8_1: D8.1(K) R20.1
NetD8_2: D8.2(A) Q4.2(D) T1.3
NetD9_1: D9.1(K) R25.1
NetQ3_1: Q3.1(G) R21.2
NetQ4_1: Q4.1(G) R29.2
NetQ4_3: Q4.3(S) R33.2 R35.2
NetR18_1: R18.1 R19.2
NetR19_1: R19.1 R22.2
NetR21_1: R21.1 U2.1(VG)
NetR23_1: R23.1 R26.2 R28.2 TP4.1
NetR26_1: R26.1 R30.2 U3.1(A)
NetR27_1: R27.1 U3.4(C)
NetR29_1: R29.1 U4.3(DRV)
NetR31_1: R31.1 R34.2 U4.6(VS)
NetR38_1: R38.1 R40.2 U6.5(EN)
NetR39_1: R39.1 R41.2 U7.5(EN)

Not connected (* = marked no-connect by the designer): T1 2 6(NC)

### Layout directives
mark named HV: NetD8_2, VBULK

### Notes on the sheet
- Pri_L = 150µH
- Pri : Bias : Sec
- L101 is placed on C19 pad. Board is cut to split "12V" polygon.
- 120 V - 375 V DC
- 24 : 5 : 3
- (near J3) 12 V @ 3.25 A
- 5 V @ 3 A
- (near J5) 3.3 V @ 3 A
- C138 and C139 placed on top to C38 and C39
- C140 placed on top of C40

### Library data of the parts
C14 = CMP-0085523-1: CAP, Aluminum Polymer, 270 µF, 16 V,+/- 20%, 0.007 ohm, TH; Manufacturer: Nichicon; AEC Category: Q200; SizeY_mm: 10; SizeArea_mm2: 100; IRMS_A: 6.1A; SizeAreaWB_mm2: 144; Polarized: Y; TaMin_C: -55°C; CompType: Capacitor; Value: 270uF; TaMax_C: 105°C; Cap_Case: 10x12.5mm; ESR_ohm: 7m; SizeZ_mm: 14; AEC Qualified: N
C15-C18 = CMP-0087257-2: CAP ALUM 680UF 20% 35V THRU HOLE; Manufacturer: Wurth Electronics; Cap_F: 680µF; Symbol Name: SYM-860080578019; AEC Qualified: No; SizeZ_mm: 21.5mm; IRMS_A: 2.26A
C20 C36 C37 = CMP-0009190-2: CAP, CERM, 10 uF, 25 V, +/- 10%, X7R, 1210; Manufacturer: MuRata; TaMin_C: -55°C; Polarized: N; SizeAreaWB_mm2: 14.7; Value1: Unknown; U/M: EA; Value: 10uF; TaMax_C: 125°C; SizeZ_mm: 2.2; SizeX_mm: 3.2; SizeY_mm: 2.5; Cap_Case: 1210; SizeArea_mm2: 8; Cap_F: 10µF; AEC Category: Q200
C21 C34 C35 = CMP-0006659-2: CAP, CERM, 0.1 uF, 25 V, +/- 10%, X7R, 0402; Manufacturer: MuRata; TaMin_C: -55°C; Polarized: N; SizeAreaWB_mm2: 3; Value1: Unknown; U/M: EA; Value: 0.1uF; TaMax_C: 125°C; SizeZ_mm: 0.6; SizeX_mm: 1; SizeY_mm: 0.5; Cap_F: 100nF; AEC Category: Q200
C22 = CMP-0078361-1: as C3 on sheet PMP21783_SCH 1
C23 = CMP-0009060-2: CAP, CERM, 0.047 uF, 500 V, +/- 10%, X7R, 1206; Manufacturer: Vishay-Vitramon; TaMin_C: -55°C; Polarized: N; SizeAreaWB_mm2: 10.92; Value1: Unknown; U/M: EA; TaMax_C: 125°C; SizeZ_mm: 1.35; SizeX_mm: 3.2; SizeY_mm: 1.6; SizeArea_mm2: 5.12; Cap_F: 47nF; AEC Category: Q200
C24 = CMP-0008482-2: CAP, CERM, 1000 pF, 100 V, +/- 5%, X7R, 1206; Manufacturer: AVX; TaMin_C: -55°C; ESR_ohm: 0.427; Polarized: N; SizeAreaWB_mm2: 10.92; Value1: 0.427 ohm; U/M: EA; Value: 1000pF; TaMax_C: 125°C; SizeZ_mm: 1.35; SizeX_mm: 3.2; SizeY_mm: 1.6; SizeArea_mm2: 5.12; Cap_F: 1nF; AEC Category: Q200
C25 = CMP-0007475-4: CAP, CERM, 2200 pF, 100 V, +/- 10%, X7R, 0603; Manufacturer: MuRata; TaMin_C: -55°C; Polarized: N; SizeAreaWB_mm2: 4.68; Value1: Unknown; U/M: EA; Value: 2200pF; TaMax_C: 125°C; SizeZ_mm: 1; SizeX_mm: 1.6; SizeY_mm: 0.8; SizeArea_mm2: 1.28; Cap_F: 2.2nF; AEC Category: Q200
C26 = CMP-0007770-2: CAP, CERM, 2.2 uF, 16 V, +/- 10%, X7R, 0805; Manufacturer: Kemet; TaMin_C: -55°C; ESR_ohm: 8m; Polarized: N; SizeAreaWB_mm2: 6.75; Value1: 0.008 ohm; U/M: EA; TaMax_C: 125°C; SizeZ_mm: 1.45; SizeX_mm: 2; SizeY_mm: 1.25; Cap_Case: 0805; SizeArea_mm2: 2.5; Cap_F: 2.2µF; IRMS_A: 15.55A; AEC Category: Q200
C27 = CMP-0086249-1: CAP, CERM, 1 µF, 50 V,+/- 10%, X7R, AEC-Q200 Grade 1, 0805; Manufacturer: MuRata; Value: 1uF; AEC Qualified: Y; AEC Category: Q200; U/M: EA; AEC Grade: 1; SizeArea_mm2: 2.5; SizeAreaWB_mm2: 6.75; SizeZ_mm: 1.45; SizeX_mm: 2; Cap_Case: 0805; TaMax_C: 125°C; Polarized: N; SizeY_mm: 1.25; TaMin_C: -55°C
C28 = CMP-0085950-1: CAP, CERM, 10 µF, 50 V,+/- 10%, X7R, AEC-Q200 Grade 1, 1206; Manufacturer: TDK; SizeZ_mm: 1.9; Value: 10uF; Cap_Case: 1206; AEC Grade: 1; TaMin_C: -55°C; U/M: EA; SizeArea_mm2: 5.12; TaMax_C: 125°C; AEC Qualified: Y; AEC Category: Q200; SizeX_mm: 3.2; SizeY_mm: 1.6; Polarized: N; SizeAreaWB_mm2: 10.92
C29 = CMP-0007039-5: CAP, CERM, 0.1 uF, 25 V, +/- 10%, X7R, 0603; Manufacturer: TDK; TaMin_C: -55°C; Polarized: N; SizeAreaWB_mm2: 4.68; Value1: Unknown; U/M: EA; Value: 0.1uF; TaMax_C: 125°C; SizeZ_mm: 1; SizeX_mm: 1.6; SizeY_mm: 0.8; SizeArea_mm2: 1.28; Cap_F: 100nF; AEC Category: Q200
C30 = CMP-0007397-4: CAP, CERM, 0.047 uF, 16 V, +/- 10%, X7R, 0603; Manufacturer: MuRata; TaMin_C: -55°C; Polarized: N; SizeAreaWB_mm2: 4.68; Value1: Unknown; U/M: EA; TaMax_C: 125°C; SizeZ_mm: 1; SizeX_mm: 1.6; SizeY_mm: 0.8; SizeArea_mm2: 1.28; Cap_F: 47nF; AEC Category: Q200
C31 = CMP-0007410-5: CAP, CERM, 0.015 uF, 25 V, +/- 10%, X7R, 0603; Manufacturer: MuRata; TaMin_C: -55°C; Polarized: N; SizeAreaWB_mm2: 4.68; Value1: Unknown; U/M: EA; TaMax_C: 125°C; SizeZ_mm: 1; SizeX_mm: 1.6; SizeY_mm: 0.8; SizeArea_mm2: 1.28; AEC Category: Q200
C32 = CMP-0007446-5: as C9 on sheet PMP21783_SCH 1
C33 = CMP-0078358-1: CAP, CERM, 2200 pF, X1 400 VAC/Y1 400 VAC, +/- 20%, Y5V, D9xL13mm; Manufacturer: Kemet; Cap_F: 2.2nF; SizeAreaWB_mm2: 121; VAC_X: 400V; SizeArea_mm2: 81; AEC Qualified: N; AEC Category: Q200; Value: 2200pF; TaMax_C: 125°C; SizeZ_mm: 13; TaMin_C: -40°C; SizeY_mm: 9; U/M: EA; Cap_Case: 9x13mm
C38-C41 C138-C140 = CMP-0008286-2: CAP, CERM, 22 uF, 10 V, +/- 20%, X5R, 0805; Manufacturer: MuRata; TaMin_C: -55°C; Polarized: N; SizeAreaWB_mm2: 6.75; Value1: Unknown; U/M: EA; Value: 22uF; TaMax_C: 85°C; SizeZ_mm: 1.45; SizeX_mm: 2; SizeY_mm: 1.25; Cap_Case: 0805; SizeArea_mm2: 2.5; Cap_F: 22µF; AEC Category: Q200
C42 = CMP-0007247-4: CAP, CERM, 150 pF, 100 V, +/- 5%, C0G/NP0, 0603; Manufacturer: MuRata; TaMin_C: -55°C; Polarized: N; SizeAreaWB_mm2: 4.68; Value1: Unknown; U/M: EA; Value: 150pF; TaMax_C: 125°C; SizeZ_mm: 1; SizeX_mm: 1.6; SizeY_mm: 0.8; Value2: 100V; SizeArea_mm2: 1.28; AEC Category: Q200
C43 = CMP-0007284-4: CAP, CERM, 82 pF, 100 V, +/- 5%, C0G/NP0, 0603; Manufacturer: MuRata; TaMin_C: -55°C; Polarized: N; SizeAreaWB_mm2: 4.68; Value1: Unknown; U/M: EA; Value: 82pF; TaMax_C: 125°C; SizeZ_mm: 1; SizeX_mm: 1.6; SizeY_mm: 0.8; Value2: 100V; SizeArea_mm2: 1.28; AEC Category: Q200
D7 = CMP-0065113-3: Diode, TVS, Uni, 200 V, 324 Vc, SMC; Manufacturer: Littelfuse; AEC Qualified: N; RJA_CperW: 75; Value1: 1500W; Ppk: 1.5kW; Vc: 324V; SizeAreaWB_mm2: 83.2686; SizeX_mm: 8.13; Ipp: 4.6A; AEC Category: Q101; SizeY_mm: 6.22; SizeZ_mm: 2.6; SizeArea_mm2: 50.5686; Vbr_Min: 224V; Vbr_Max: 247V
D8 = CMP-0076882-2: Diode, Ultrafast, 1000 V, 1 A, SMA; Manufacturer: Diodes Inc.; AEC Category: Q101; Value2: 1.7V; SizeZ_mm: 2.87; Green_REACh: Incomplete; Value: 1000V; Value1: 1A; SizeAreaWB_mm2: 37.3428; Green_Lifecycle: Not Set; RJC_CperW: 30.0; SizeX_mm: 5.59; SizeArea_mm2: 16.3228; Vr_V: 1kV; TJmax_C: 150°C; SizeY_mm: 2.92
D9 = CMP-0028782-2: Diode, Schottky, 100 V, 1 A, AEC-Q101, SOD-123W; Manufacturer: Nexperia; Green_REACh: Incomplete; SizeX_mm: 3.5; SizeAreaWB_mm2: 12.15; SizeY_mm: 1.7; AEC Category: Q101; Value: 100V; SizeZ_mm: 1; AEC Qualified: Y; TJmax_C: 175°C; SizeArea_mm2: 5.95; Vf_V: 770mV; Io_A: 1A; Value2: 0.77V; Green_Lifecycle: Not Set
H3 = CMP-0004019-1: Heat Sink, TO-220 Vertical; Manufacturer: Aavid
J3-J5 = CMP-0054822-2: Terminal Block, 2x1, 3.81mm, 24-16 AWG, 10A, 300VAC, TH; Manufacturer: Wurth Elektronik; CT: TRUE; CNHeader: FALSE; Green_Lifecycle: Active; Green_REACh: Passed
L5 L6 = CMP-0064002-1: Inductor, Shielded Drum Core, Ferrite, 3.3 uH, 14 A, 0.0054 ohm, SMD; Manufacturer: Wurth Elektronik; Isat: 15.5A @ 30% inductance drop; Irms: 14A @ 50C rise; Green_Lifecycle: Active; SizeAreaWB_mm2: 154.8; DCR_ohm: 5.4m; Green_REACh: Passed; Value: 3.3uH; Imax_A: 14A; SizeZ_mm: 9.7; SizeX_mm: 10.9; SizeY_mm: 10; SizeArea_mm2: 109; Ind_H: 3.3µH; AEC Category: Q200
L101 = CMP-0063902-1: Inductor, Shielded Drum Core, Ferrite, 300 nH, 24 A, 0.0003 ohm, SMD; Manufacturer: Wurth Elektronik; Isat: 24A @ 20% inductance drop; Irms: 26A @ 50C rise; Green_Lifecycle: Active; SizeAreaWB_mm2: 153.75; DCR_ohm: 300µ; Green_REACh: Passed; Value: 300nH; Imax_A: 24A; SizeZ_mm: 5.5; SizeX_mm: 10.5; SizeY_mm: 10.3; SizeArea_mm2: 108.15; AEC Category: Q200
LOGO5 = CMP-0074835-1: as LOGO2 on sheet PMP21783_SCH 1
LOGO6 = CMP-0074837-1: as LOGO1 on sheet PMP21783_SCH 1
Q3 = CMP-0000955-1: MOSFET, N-CH, 100 V, 100 A, KCS0003B (TO-220-3); Alternate Manufacturer: None; Manufacturer: Texas Instruments; SizeZ_mm: 20.45; ChType: N; Value2: 38 nC; VdsMax_V: 100V; SizeX_mm: 4.55; SizeY_mm: 10.16; Vgs_V: 20V; QgTyp_nC: 38; Value: 100V; SizeArea_mm2: 46.228; AEC Category: Q101; IdsMax_A: 100A; SizeAreaWB_mm2: 79.648; U/M: EA
Q4 = CMP-0081521-2: MOSFET, N-CH, 700 V, 12.5 A, DPAK; Alternate Manufacturer: None; Manufacturer: Infineon Technologies; ChType: N; Value1: ? ohm; ChMode: Enhancement; Value: 700V; SizeArea_mm2: 64.8114; IdsMax_A: 12.5A; Value2: 16.4 nC; SizeX_mm: 9.91; QgTyp_nC: 16.4; AEC Category: Q101; Vgs_V: 16V; SizeZ_mm: 2.29; SizeAreaWB_mm2: 101.7114; SizeY_mm: 6.54
R18 R19 R22 = CMP-0021616-2: RES, 2.00 M, 1%, 0.125 W, AEC-Q200 Grade 0, 0805; Manufacturer: Panasonic; Power_W: 125mW; TempCo: 100 ppm/C; Value_Code: 2M00; U/M: EA; Value: 2.00Meg; EIA_Code: E96; Res_ohm: 2M; SizeX_mm: 2; SizeY_mm: 1.25; SizeZ_mm: 1.45; Value2: 0.125W; SizeArea_mm2: 2.5; AEC Qualified: Y; VDC_V: 150V; AEC Grade: 0; AEC Category: Q200
R20 = CMP-0018573-3: RES, 0, 5%, 0.25 W, AEC-Q200 Grade 0, 1206; Manufacturer: Vishay-Dale; Power_W: 250mW; TempCo: 200 ppm/C; Value_Code: 0000; Value: 0; EIA_Code: E24; SizeX_mm: 3.2; SizeY_mm: 1.6; SizeZ_mm: 1.35; Value2: 0.25W; SizeArea_mm2: 5.12; AEC Qualified: Y; VDC_V: 200V; AEC Category: Q200
R21 R27 R29 = CMP-0025697-4: RES, 0, 5%, 0.1 W, AEC-Q200 Grade 0, 0603; Manufacturer: Vishay-Dale; Power_W: 100mW; TempCo: 200 ppm/C; Value_Code: 0000; Value: 0; EIA_Code: E24; SizeX_mm: 1.6; SizeY_mm: 0.8; SizeZ_mm: 1; Value2: 0.1W; SizeArea_mm2: 1.28; AEC Qualified: Y; VDC_V: 75V; AEC Category: Q200
R23 R42 R43 = CMP-0022448-4: RES, 49.9, 1%, 0.1 W, AEC-Q200 Grade 0, 0603; Manufacturer: Vishay-Dale; Power_W: 100mW; TempCo: 100 ppm/C; Value_Code: 49R9; Value: 49.9; EIA_Code: E96; SizeX_mm: 1.6; SizeY_mm: 0.8; SizeZ_mm: 1; Value2: 0.1W; SizeArea_mm2: 1.28; AEC Qualified: Y; VDC_V: 75V; AEC Category: Q200; AEC Grade: 0
R24 = CMP-0018576-3: RES, 10 k, 5%, 0.25 W, AEC-Q200 Grade 0, 1206; Manufacturer: Vishay-Dale; Power_W: 250mW; TempCo: 200 ppm/C; Value_Code: 10k0; Value: 10k; EIA_Code: E24; SizeX_mm: 3.2; SizeY_mm: 1.6; SizeZ_mm: 1.35; Value2: 0.25W; SizeArea_mm2: 5.12; AEC Qualified: Y; VDC_V: 200V; AEC Category: Q200; AEC Grade: 0
R25 = CMP-0025743-4: RES, 1.0, 5%, 0.1 W, AEC-Q200 Grade 0, 0603; Manufacturer: Vishay-Dale; Power_W: 100mW; TempCo: 200 ppm/C; Value_Code: 1R00; Value: 1.0; EIA_Code: E24; Res_ohm: 1; SizeX_mm: 1.6; SizeY_mm: 0.8; Value2: 0.1W; SizeArea_mm2: 1.28; AEC Qualified: Y; VDC_V: 75V; AEC Category: Q200; AEC Grade: 0
R26 = CMP-0022269-4: RES, 2.05 k, 1%, 0.1 W, AEC-Q200 Grade 0, 0603; Manufacturer: Vishay-Dale; Power_W: 100mW; TempCo: 100 ppm/C; Value_Code: 2k05; Value: 2.05k; EIA_Code: E96; SizeX_mm: 1.6; SizeY_mm: 0.8; SizeZ_mm: 1; Value2: 0.1W; SizeArea_mm2: 1.28; AEC Qualified: Y; VDC_V: 75V; AEC Category: Q200; AEC Grade: 0
R28 = CMP-0022659-4: RES, 95.3 k, 1%, 0.1 W, AEC-Q200 Grade 0, 0603; Manufacturer: Vishay-Dale; Power_W: 100mW; TempCo: 100 ppm/C; Value_Code: 95k3; Value: 95.3k; EIA_Code: E96; SizeX_mm: 1.6; SizeY_mm: 0.8; SizeZ_mm: 1; Value2: 0.1W; SizeArea_mm2: 1.28; AEC Qualified: Y; VDC_V: 75V; AEC Category: Q200; AEC Grade: 0
R30 = CMP-0022109-5: as R9 on sheet PMP21783_SCH 1
R31 = CMP-0021996-4: RES, 107 k, 1%, 0.1 W, AEC-Q200 Grade 0, 0603; Manufacturer: Vishay-Dale; Power_W: 100mW; TempCo: 100 ppm/C; Value: 107k; EIA_Code: E96; SizeX_mm: 1.6; SizeY_mm: 0.8; SizeZ_mm: 1; Value2: 0.1W; SizeArea_mm2: 1.28; AEC Qualified: Y; VDC_V: 75V; AEC Category: Q200; AEC Grade: 0
R32 = CMP-0022334-4: RES, 32.4 k, 1%, 0.1 W, AEC-Q200 Grade 0, 0603; Manufacturer: Vishay-Dale; Power_W: 100mW; TempCo: 100 ppm/C; Value_Code: 32k4; Value: 32.4k; EIA_Code: E96; SizeX_mm: 1.6; SizeY_mm: 0.8; SizeZ_mm: 1; Value2: 0.1W; SizeArea_mm2: 1.28; AEC Qualified: Y; VDC_V: 75V; AEC Category: Q200; AEC Grade: 0
R33 = CMP-0022125-4: RES, 1.47 k, 1%, 0.1 W, AEC-Q200 Grade 0, 0603; Manufacturer: Vishay-Dale; Power_W: 100mW; TempCo: 100 ppm/C; Value_Code: 1k47; Value: 1.47k; EIA_Code: E96; SizeX_mm: 1.6; SizeY_mm: 0.8; SizeZ_mm: 1; Value2: 0.1W; SizeArea_mm2: 1.28; AEC Qualified: Y; VDC_V: 75V; AEC Category: Q200; AEC Grade: 0
R34 = CMP-0022090-4: RES, 17.8 k, 1%, 0.1 W, AEC-Q200 Grade 0, 0603; Manufacturer: Vishay-Dale; Power_W: 100mW; TempCo: 100 ppm/C; Value_Code: 17k8; Value: 17.8k; EIA_Code: E96; SizeX_mm: 1.6; SizeY_mm: 0.8; SizeZ_mm: 1; Value2: 0.1W; SizeArea_mm2: 1.28; AEC Qualified: Y; VDC_V: 75V; AEC Category: Q200; AEC Grade: 0
R35 = CMP-0015783-2: RES, 0.25, 1%, 2 W, 2512; Manufacturer: Stackpole Electronics Inc; Power_W: 2W; TempCo: 200 ppm/C; Value_Code: R250; U/M: EA; Value: 0.25; SizeX_mm: 6.3; SizeY_mm: 3.2; SizeZ_mm: 0.71; SizeArea_mm2: 20.16; AEC Category: Q200
R36 = CMP-0022449-4: RES, 4.02 k, 1%, 0.1 W, AEC-Q200 Grade 0, 0603; Manufacturer: Vishay-Dale; Power_W: 100mW; TempCo: 100 ppm/C; Value_Code: 4k02; Value: 4.02k; EIA_Code: E96; SizeX_mm: 1.6; SizeY_mm: 0.8; SizeZ_mm: 1; Value2: 0.1W; SizeArea_mm2: 1.28; AEC Qualified: Y; VDC_V: 75V; AEC Category: Q200; AEC Grade: 0
R37 = CMP-0022016-4: RES, 11.0 k, 1%, 0.1 W, AEC-Q200 Grade 0, 0603; Manufacturer: Vishay-Dale; Power_W: 100mW; TempCo: 100 ppm/C; Value_Code: 11k0; Value: 11.0k; EIA_Code: E96; Res_ohm: 11k; SizeX_mm: 1.6; SizeY_mm: 0.8; SizeZ_mm: 1; Value2: 0.1W; SizeArea_mm2: 1.28; AEC Qualified: Y; VDC_V: 75V; AEC Category: Q200; AEC Grade: 0
R38 R39 = CMP-0022480-4: RES, 511 k, 1%, 0.1 W, AEC-Q200 Grade 0, 0603; Manufacturer: Vishay-Dale; Power_W: 100mW; TempCo: 100 ppm/C; Value: 511k; EIA_Code: E96; SizeX_mm: 1.6; SizeY_mm: 0.8; SizeZ_mm: 1; Value2: 0.1W; SizeArea_mm2: 1.28; AEC Qualified: Y; VDC_V: 75V; AEC Category: Q200; AEC Grade: 0
R40 R41 = CMP-0021994-4: RES, 105 k, 1%, 0.1 W, AEC-Q200 Grade 0, 0603; Manufacturer: Vishay-Dale; Power_W: 100mW; TempCo: 100 ppm/C; Value: 105k; EIA_Code: E96; SizeX_mm: 1.6; SizeY_mm: 0.8; SizeZ_mm: 1; Value2: 0.1W; SizeArea_mm2: 1.28; AEC Qualified: Y; VDC_V: 75V; AEC Category: Q200; AEC Grade: 0
R44 = CMP-0022494-4: RES, 54.9 k, 1%, 0.1 W, AEC-Q200 Grade 0, 0603; Manufacturer: Vishay-Dale; Power_W: 100mW; TempCo: 100 ppm/C; Value_Code: 54k9; Value: 54.9k; EIA_Code: E96; SizeX_mm: 1.6; SizeY_mm: 0.8; SizeZ_mm: 1; Value2: 0.1W; SizeArea_mm2: 1.28; AEC Qualified: Y; VDC_V: 75V; AEC Category: Q200; AEC Grade: 0
R45 = CMP-0022339-4: RES, 33.2 k, 1%, 0.1 W, AEC-Q200 Grade 0, 0603; Manufacturer: Vishay-Dale; Power_W: 100mW; TempCo: 100 ppm/C; Value_Code: 33k2; Value: 33.2k; EIA_Code: E96; SizeX_mm: 1.6; SizeY_mm: 0.8; SizeZ_mm: 1; Value2: 0.1W; SizeArea_mm2: 1.28; AEC Qualified: Y; VDC_V: 75V; AEC Category: Q200; AEC Grade: 0
R46 R47 = CMP-0021998-4: as R16 on sheet PMP21783_SCH 1
T1 = CMP-0085998-1: Transformer, 150 uH, TH; Manufacturer: Renco Electronics; Lp: 150; LeakageInd_H: 6µH; AEC Qualified: N; SizeZ_mm: 20.828; Ns1toNp: 0.125; Ind_H: 150µH; SizeX_mm: 36.83; AEC Category: Q200; SizeAreaWB_mm2: 1152.70738; Rsec1_ohm: 3.5m; SizeArea_mm2: 1019.67538; DCR_ohm: 0.075; Value: 150uH; SizeY_mm: 27.686
TP2 TP3 = CMP-0055147-1: as TP1 on sheet PMP21783_SCH 1
TP4 TP7 TP8 = CMP-0055139-1: Test Point, Miniature, White, TH; Manufacturer: Keystone; CNHeader: FALSE; Green_Lifecycle: Active; Green_REACh: Passed; ContactFinish: Silver; CT: TRUE
TP5 TP6 = CMP-0055148-1: Test Point, Multipurpose, Black, TH; Manufacturer: Keystone; CNHeader: FALSE; Green_Lifecycle: Active; Green_REACh: Passed; ContactFinish: Silver; CT: TRUE
U2 = CMP-0013050-3: High-Frequency Multi-Mode Synchronous Rectifier Controller, DBV0005A (SOT-23-5); Manufacturer: Texas Instruments; Alternate PartNumber: UCC24612-1DBVT; SizeX_mm: 2.8; SizeY_mm: 2.9; CompType: IC; SizeZ_mm: 1.45; SizeArea_mm2: 8.12; SizeAreaWB_mm2: 14.82; AEC Category: Q200; AEC Qualified: N
U3 = CMP-0006187-3: Optocoupler, 5.3 kV, 50-600% CTR, TH; Manufacturer: Vishay-Semiconductor; CTR (Max): 200%; SizeAreaWB_mm2: 71.064; CTR (Min): 100%; SizeZ_mm: 5; SizeX_mm: 8.8; SizeY_mm: 4.58; SizeArea_mm2: 40.304; Voltage_Isolation_Vrms: 5.3kV
U4 = CMP-0078369-2: High-Efficiency Low-Cost Flyback Controller with Secondary-Side Regulation, DBV0006A (SOT-23-6); Manufacturer: Texas Instruments; SizeZ_mm: 1.45; SizeX_mm: 2.8; SizeY_mm: 2.9; AEC Category: Q200; AEC Qualified: N; SizeArea_mm2: 8.12; CompType: IC; SizeAreaWB_mm2: 14.82
U5 = CMP-0033139-1: Low-Voltage Adjustable Precision Shunt Regulator, 80 mA, -40 to 125 degC, 3-pin SOT-23 (DBZ), Green (RoHS & no Sb/Br); Manufacturer: Texas Instruments; VO Adj(Max)(V): 18; Initial Accuracy @ 25/deg C(%): 1; Iout/Iz(Max)(mA): 80; SubFamily: Shunt Voltage Reference; Rating: Catalog; VO Adj(Min)(V): 1.24; Temp Coeff(Max)(ppm/ degree C): 129
U6 = CMP-0074006-2: 4.5V to 17V Input, 4A Output, Synchronous Step-Down Converter, DDC0006A (SOT-23-T-6); Alternate PartNumber: TPS564201DDCT; Alternate Manufacturer: Texas Instruments; Green_Lifecycle: Active; SizeAreaWB_mm2: 10.4675; Green_REACh: Passed; U/M: EA; SizeZ_mm: 0.87; SizeX_mm: 1.65; SizeY_mm: 2.95; SizeArea_mm2: 4.8675; CompType: IC
U7 = CMP-0073977-2: 4.5-V to 28-V Input, 3-A Output, EMI Friendly Synchronous Step-Down Converter, DDC0006A (SOT-23-T-6); Alternate PartNumber: TPS54302DDCT; Manufacturer: Texas Instruments; SizeZ_mm: 0.87; SizeX_mm: 1.65; SizeY_mm: 2.95; SizeArea_mm2: 4.8675; CompType: IC; U/M: EA; SizeAreaWB_mm2: 10.4675

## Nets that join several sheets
GND: PMP21783_SCH 1 (25 pins), PMP21783_SCH 2 (12 pins)
VBULK: PMP21783_SCH 1 (L2.2), PMP21783_SCH 2 (7 pins)
AUX: PMP21783_SCH 1 (D2.2), PMP21783_SCH 2 (D9.2 R31.2 T1.5)

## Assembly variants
001: not fitted FID1 FID2 FID3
